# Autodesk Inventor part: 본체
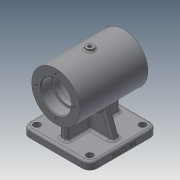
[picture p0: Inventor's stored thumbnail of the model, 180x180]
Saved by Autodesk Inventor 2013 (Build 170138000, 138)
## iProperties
Created: 2019-06
Part Number: 본체
Material: Generic
Document SubType Name: Modeling
Designer: user
Density: 1 g/cm^3
Author: user
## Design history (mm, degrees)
sketch "스케치1"
  geometry: C1 r 32 at (0, 0); 1 further point
  constraints: 1 centre point, 1 coincident
  dimensions: "d0" = 64 diameter of C1
extrude "돌출1" new body sketch "스케치1" stored distance "d1" = 90; taper "d2" = 0 deg
sketch "스케치2"
  geometry: L1 (32, 45)-(-32, 45) reference; L2 (-32, -45)-(32, -45) reference; L3 (0, 45)-(0, -45); L4 (20, 45)-(20, 30); L5 (20, 30)-(17, 30); L6 (17, 30)-(17, 24); L7 (17, 24)-(25, 24); L8 (25, 24)-(25, -24); L9 (25, -24)-(17, -24); L10 (17, -24)-(17, -30); L11 (17, -30)-(20, -30); L12 (20, -30)-(20, -45); 1 further point
  constraints: 20 end point, 5 perpendicular, 4 parallel, 2 midpoint, 2 point on line
  dimensions: "d3" = 15 distance of L4.start L4.end; "d5" = 15 distance of L11.end L12.end; "d6" = 6 distance of L5.end L6.end; "d7" = 6 distance of L9.end L10.end; "d8" = 40 diameter of L4 L3; "d9" = 40 diameter of L12 L3; "d10" = 50 diameter of L8 L3; "d11" = 34 diameter of L6 L3; "d12" = 34 diameter of L10 L3
revolve "회전1" sketch "스케치2" stored, may be unused: angle "d13" = 90 deg
chamfer "모따기1" distance "d14" = 1; stored, may be unused: second distance "d15" = 2, angle "d16" = 45 deg
fillet "모깎기1" dims "d17" = 3
fillet "모깎기2" dims "d18" = 0.6
sketch "스케치3"
  geometry: L1 (0, 0)-(0, 25); C1 r 21 at (0, 0) reference; 1 further point
  constraints: 2 end point, 1 coincident, 1 vertical
  dimensions: "d19" = 25 distance of L1.start L1.end
hole "구멍1" sketch "스케치3" at (0, 25) diameter "d20" = 3.242; stored, may be unused: countersink angle "d24" = 90 deg, drill point angle "d26" = 118 deg; dims "d21" = 7, "d22" = 4, "d23" = 2, "d25" = 9
node "작업 평면1"
sketch "스케치4"
  geometry: L1 (45, -45)-(-45, -45); L2 (-45, -45)-(-45, 45); L3 (-45, 45)-(45, 45); L4 (45, 45)-(45, -45); L5 (45, -45)-(-45, 45); L6 (-45, -45)-(45, 45); 1 further point
  constraints: 12 end point, 2 midpoint, 2 parallel, 1 horizontal, 1 perpendicular
  dimensions: "d31" = 90 distance of L2.end L3.end; "d32" = 90 distance of L1.end L2.end
extrude "돌출2" join sketch "스케치4" distance "d33" = 10; taper "d34" = 0 deg
fillet "모깎기3" dims "d35" = 10
sketch "스케치5"
  geometry: A1 r 10 centre (-35, -35) between (-45, -35) and (-35, -45) reference; A2 r 10 centre (35, -35) between (35, -45) and (45, -35) reference; A3 r 10 centre (35, 35) between (45, 35) and (35, 45) reference; A4 r 10 centre (-35, 35) between (-35, 45) and (-45, 35) reference; 5 further points
  constraints: 4 coincident
hole "구멍2" sketch "스케치5" at (-35, 35), (35, 35), (35, -35), (-35, -35) diameter "d36" = 9; stored, may be unused: countersink angle "d40" = 90 deg, drill point angle "d42" = 118 deg; dims "d37" = 7, "d38" = 4, "d39" = 2, "d41" = 9
sketch "스케치6"
  geometry: L1 (5, -35)-(-5, -35); L2 (-5, -35)-(-5, 35); L3 (-5, 35)-(5, 35); L4 (5, 35)-(5, -35); L5 (5, -35)-(-5, 35); L6 (-5, -35)-(5, 35); 1 further point
  constraints: 12 end point, 2 midpoint, 2 parallel, 1 horizontal, 1 perpendicular
  dimensions: "d43" = 10 distance of L2.end L3.end; "d44" = 70 distance of L1.end L2.end
extrude "돌출3" join sketch "스케치6" stored distance "d45" = 10; taper "d46" = 0 deg
sketch "스케치7"
  geometry: L1 (35, -55)-(-35, -55) reference; L2 (23.058, -22.189)-(35, -55); L3 (45, -55)-(45, -65) reference; 2 further points
  constraints: 2 end point, 1 point on line, 2 other
  dimensions: "d47" = 110 deg angle of L1 L2; "d48" = 10 distance of L3.start L2.end
feature "리브1" sketch "스케치7" dims "d49" = 1, "d50" = 10, "d51" = 0, "d52" = 0, "d53" = 1, "d54" = 1
node "작업 평면2"
sketch "스케치8"
  geometry: C1 r 5 at (0, 0); 1 further point
  constraints: 1 centre point, 1 coincident
  dimensions: "d56" = 10 diameter of C1
extrude "돌출4" join sketch "스케치8" stored distance "d57" = 10; taper "d58" = 0 deg
sketch "스케치9"
  geometry: C1 r 5 at (0, 0) reference; 1 further point
  constraints: 1 coincident
hole "구멍3" sketch "스케치9" at (0, 0) diameter "d59" = 4.917; stored, may be unused: countersink angle "d63" = 90 deg, drill point angle "d65" = 118 deg; dims "d60" = 20, "d61" = 4, "d62" = 2, "d64" = 9
fillet "모깎기4" dims "d66" = 2
sketch "스케치11"
  geometry: L1 (40, -40)-(-40, -40); L2 (-40, -40)-(-40, 40); L3 (-40, 40)-(40, 40); L4 (40, 40)-(40, -40); C1 r 4.5 at (-35, 35) reference; C2 r 4.5 at (35, -35) reference; C3 r 4.5 at (-35, -35) reference; C4 r 4.5 at (35, 35) reference; 3 further points
  constraints: 8 end point, 2 midpoint, 2 parallel, 1 horizontal, 1 horizontal alignment, 1 perpendicular, 1 vertical alignment
  dimensions: "d73" = 80 distance of L2.end L3.end; "d74" = 80 distance of L1.end L2.end
extrude "돌출5" cut sketch "스케치11" distance "d76" = 5; taper "d77" = 0 deg
sketch "스케치12"
  geometry: C1 r 4.5 at (35, 35) reference; C2 r 4.5 at (-35, -35) reference; C3 r 4.5 at (35, -35) reference; C4 r 4.5 at (-35, 35) reference; C5 r 10 at (35, -35); C6 r 10 at (-35, -35); C7 r 10 at (-35, 35); C8 r 10 at (35, 35); 1 further point
  constraints: 4 centre point, 4 coincident
  dimensions: "d78" = 20 diameter of C5; "d79" = 20 diameter of C6; "d80" = 20 diameter of C7; "d81" = 20 diameter of C8
extrude "돌출6" join sketch "스케치12" distance "d82" = 5; taper "d83" = 0 deg
fillet "모깎기5" dims "d84" = 3
fillet "모깎기6" dims "d85" = 3
fillet "모깎기7" dims "d86" = 3
fillet "모깎기8" dims "d87" = 3
fillet "모깎기9" dims "d88" = 3
sketch "스케치13"
  geometry: L1 (-10, 7)-(-10, 0) reference; 2 further points
  constraints: 1 other
  dimensions: "d89" = 45 distance from line of L1 point (35, 4); "d90" = 4 vertical distance of L1.end point (35, 4)
feature "엠보싱1" sketch "스케치13" dims "d91" = 0.5, "d92" = 0
node "솔리드1"
pattern_circular "원형 패턴1" dims angle "d28" = 360 deg
mirror "대칭1"
mirror "대칭2"
other parameters: "d30" = -65
